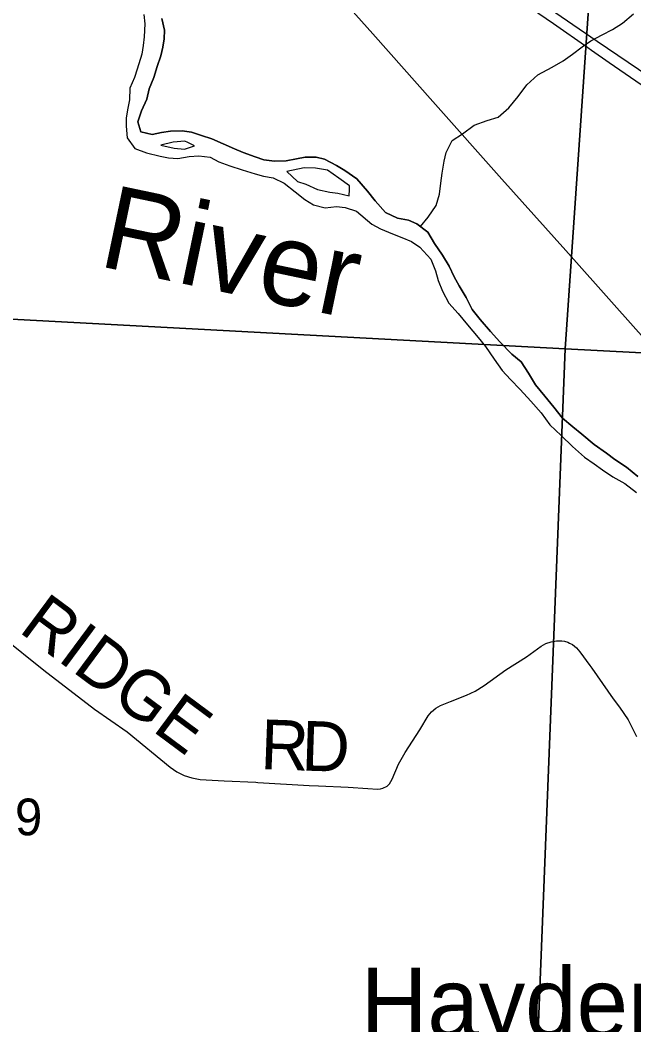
# Model space of a CAD drawing. Extents: x 0 to 34, y 0 to 22.
# Drawn here: x 5.957 to 6.658, y 19.04 to 20.186 of the extents above; entities that cross this region are included whole.
import ezdxf

# ---------------------------------------------------------------- set-up
doc = ezdxf.new("R2010")
doc.units = 0
for name, color, linetype in [('GM_X_Corporation', 7, 'Continuous'), ('GM_X_Major_River', 7, 'Continuous'), ('GM_X_Major_River_Text', 7, 'Continuous'), ('GM_X_Minor_River', 7, 'Continuous'), ('GM_X_Rail_Line', 7, 'Continuous'), ('GM_X_Section_Text', 7, 'Continuous'), ('GM_X_Township_Road', 7, 'Continuous'), ('GM_X_Township_Road_Text', 7, 'Continuous'), ('GM_X_Unincorporated_Text', 7, 'Continuous'), ('GM_X_US_Route', 7, 'Continuous')]:
    doc.layers.add(name, color=color, linetype=linetype)

msp = doc.modelspace()

# ---------------------------------------------------------------- linework, layer by layer
at = {"layer": 'GM_X_Corporation'}
for points in [[(5.6551, 20.8957), (6.6504, 20.8365), (6.5798, 19.8114), (5.5855, 19.8646)], [(6.6504, 20.8365), (7.0809, 20.8104), (7.4778, 20.7864), (7.6585, 20.7741), (7.5941, 19.7583), (6.5798, 19.8114)], [(5.5855, 19.8646), (6.5798, 19.8114), (6.5391, 18.7835), (5.5263, 18.8526)], [(6.5798, 19.8114), (7.5941, 19.7583), (7.5958, 19.6386), (7.5162, 18.7157), (6.5391, 18.7835)]]:
    msp.add_lwpolyline(points, close=True, dxfattribs=at)
at = {"layer": 'GM_X_Major_River'}
for p, q in [((6.0988, 20.1928), (6.0997, 20.1822)), ((6.1225, 20.1749), (6.1193, 20.1881)), ((6.0997, 20.1822), (6.0991, 20.1674)), ((6.0991, 20.1674), (6.098, 20.1572)), ((6.1204, 20.1555), (6.1218, 20.165)), ((6.1218, 20.165), (6.1225, 20.1749)), ((6.098, 20.1572), (6.0966, 20.1473)), ((6.1182, 20.1456), (6.1204, 20.1555)), ((6.0966, 20.1473), (6.0911, 20.1302)), ((6.1141, 20.1335), (6.1182, 20.1456)), ((6.1101, 20.1209), (6.1141, 20.1335)), ((6.0881, 20.1207), (6.0829, 20.1086)), ((6.0911, 20.1302), (6.0881, 20.1207)), ((6.1049, 20.108), (6.1101, 20.1209)), ((6.0829, 20.1086), (6.0823, 20.0953)), ((6.1023, 20.0962), (6.1049, 20.108)), ((6.096, 20.0829), (6.1023, 20.0962)), ((6.0805, 20.0858), (6.0787, 20.0748)), ((6.0823, 20.0953), (6.0805, 20.0858)), ((6.0787, 20.0748), (6.0784, 20.0653)), ((6.092, 20.0704), (6.096, 20.0829)), ((6.0784, 20.0653), (6.0796, 20.0521)), ((6.0955, 20.0587), (6.092, 20.0704)), ((6.0796, 20.0521), (6.0884, 20.04)), ((6.1084, 20.0557), (6.0955, 20.0587)), ((6.1189, 20.0581), (6.1084, 20.0557)), ((6.1291, 20.0597), (6.1189, 20.0581)), ((6.1424, 20.0598), (6.1291, 20.0597)), ((6.153, 20.0584), (6.1424, 20.0598)), ((6.1644, 20.0547), (6.153, 20.0584)), ((6.1765, 20.0507), (6.1644, 20.0547)), ((6.2023, 20.0395), (6.1765, 20.0507)), ((6.0884, 20.04), (6.1017, 20.0348)), ((6.1323, 20.0472), (6.118, 20.0438)), ((6.118, 20.0438), (6.1335, 20.0401)), ((6.1455, 20.0481), (6.1323, 20.0472)), ((6.1335, 20.0401), (6.1452, 20.039)), ((6.1452, 20.039), (6.1565, 20.0429)), ((6.1488, 20.0466), (6.1455, 20.0481)), ((6.1565, 20.0429), (6.1488, 20.0466)), ((6.2122, 20.0351), (6.2023, 20.0395)), ((6.1017, 20.0348), (6.1173, 20.0312)), ((6.1173, 20.0312), (6.1271, 20.029)), ((6.1271, 20.029), (6.1374, 20.0283)), ((6.1374, 20.0283), (6.1506, 20.0307)), ((6.1506, 20.0307), (6.1615, 20.0316)), ((6.1615, 20.0316), (6.1744, 20.0298)), ((6.1744, 20.0298), (6.1843, 20.0246)), ((6.2259, 20.0303), (6.2122, 20.0351)), ((6.2357, 20.027), (6.2259, 20.0303)), ((6.2732, 20.0281), (6.2611, 20.0257)), ((6.283, 20.03), (6.2732, 20.0281)), ((6.2955, 20.0298), (6.283, 20.03)), ((6.305, 20.0276), (6.2955, 20.0298)), ((6.3187, 20.0205), (6.305, 20.0276)), ((6.1843, 20.0246), (6.1968, 20.0202)), ((6.1968, 20.0202), (6.2109, 20.0154)), ((6.2479, 20.0252), (6.2357, 20.027)), ((6.2611, 20.0257), (6.2479, 20.0252)), ((6.282, 20.0179), (6.262, 20.0136)), ((6.2949, 20.0173), (6.282, 20.0179)), ((6.3085, 20.0151), (6.2949, 20.0173)), ((6.3282, 20.0149), (6.3187, 20.0205)), ((6.2109, 20.0154), (6.2257, 20.011)), ((6.2257, 20.011), (6.2355, 20.0084)), ((6.2355, 20.0084), (6.2465, 20.0062)), ((6.2465, 20.0062), (6.2591, 20.0003)), ((6.262, 20.0136), (6.2742, 20.0023)), ((6.3214, 20.0061), (6.3085, 20.0151)), ((6.3336, 19.9972), (6.3214, 20.0061)), ((6.3419, 20.0052), (6.3282, 20.0149)), ((6.3541, 19.9913), (6.3419, 20.0052)), ((6.2591, 20.0003), (6.2716, 19.9905)), ((6.2742, 20.0023), (6.2837, 19.999)), ((6.2837, 19.999), (6.297, 19.993)), ((6.297, 19.993), (6.311, 19.9901)), ((6.3335, 19.9929), (6.3336, 19.9972)), ((6.2716, 19.9905), (6.2827, 19.9815)), ((6.2827, 19.9815), (6.2926, 19.9756)), ((6.311, 19.9901), (6.3204, 19.9887)), ((6.3204, 19.9887), (6.3333, 19.9858)), ((6.3333, 19.9858), (6.3335, 19.9929)), ((6.3629, 19.98), (6.3541, 19.9913)), ((6.2926, 19.9756), (6.3058, 19.9723)), ((6.3058, 19.9723), (6.3187, 19.9735)), ((6.3187, 19.9735), (6.3285, 19.9725)), ((6.3285, 19.9725), (6.3414, 19.9684)), ((6.3747, 19.9668), (6.3629, 19.98)), ((6.3414, 19.9684), (6.359, 19.9534)), ((6.3884, 19.9605), (6.3747, 19.9668)), ((6.4009, 19.958), (6.3884, 19.9605)), ((6.359, 19.9534), (6.3689, 19.9482)), ((6.3689, 19.9482), (6.3825, 19.9423)), ((6.4104, 19.9539), (6.4009, 19.958)), ((6.423, 19.9445), (6.4104, 19.9539)), ((6.3825, 19.9423), (6.3935, 19.9382)), ((6.3935, 19.9382), (6.4042, 19.9338)), ((6.4307, 19.9313), (6.423, 19.9445)), ((6.4042, 19.9338), (6.4137, 19.9274)), ((6.4137, 19.9274), (6.4263, 19.9135)), ((6.4399, 19.9182), (6.4307, 19.9313)), ((6.4263, 19.9135), (6.4317, 19.9003)), ((6.4472, 19.9057), (6.4399, 19.9182)), ((6.4529, 19.8933), (6.4472, 19.9057)), ((6.4317, 19.9003), (6.4348, 19.8893)), ((6.4587, 19.8831), (6.4529, 19.8933)), ((6.4348, 19.8893), (6.4398, 19.8769)), ((6.4668, 19.8699), (6.4587, 19.8831)), ((6.4398, 19.8769), (6.4468, 19.8633)), ((6.4737, 19.8563), (6.4668, 19.8699)), ((6.4468, 19.8633), (6.4575, 19.8516)), ((6.4829, 19.8447), (6.4737, 19.8563)), ((6.4575, 19.8516), (6.4682, 19.8388)), ((6.4944, 19.8311), (6.4829, 19.8447)), ((6.4682, 19.8388), (6.4804, 19.8242)), ((6.4804, 19.8242), (6.4888, 19.814)), ((6.5054, 19.8191), (6.4944, 19.8311)), ((6.4888, 19.814), (6.4988, 19.7993)), ((6.5188, 19.8052), (6.5054, 19.8191)), ((6.4988, 19.7993), (6.508, 19.7865)), ((6.5295, 19.7966), (6.5188, 19.8052)), ((6.5379, 19.7834), (6.5295, 19.7966)), ((6.508, 19.7865), (6.5175, 19.7764)), ((6.5175, 19.7764), (6.5286, 19.7647)), ((6.546, 19.7702), (6.5379, 19.7834)), ((6.5286, 19.7647), (6.5408, 19.7516)), ((6.5567, 19.7574), (6.546, 19.7702)), ((6.567, 19.7446), (6.5567, 19.7574)), ((6.5408, 19.7516), (6.5523, 19.7381)), ((6.5769, 19.7322), (6.567, 19.7446)), ((6.5523, 19.7381), (6.5623, 19.7245)), ((6.5884, 19.7221), (6.5769, 19.7322)), ((6.5623, 19.7245), (6.5752, 19.7125)), ((6.5987, 19.7138), (6.5884, 19.7221)), ((6.5752, 19.7125), (6.5882, 19.6997)), ((6.6131, 19.7022), (6.5987, 19.7138)), ((6.5882, 19.6997), (6.6019, 19.6877)), ((6.6269, 19.6921), (6.6131, 19.7022)), ((6.6019, 19.6877), (6.613, 19.6802)), ((6.6364, 19.685), (6.6269, 19.6921)), ((6.6497, 19.6764), (6.6364, 19.685)), ((6.613, 19.6802), (6.6225, 19.6731)), ((6.6225, 19.6731), (6.6343, 19.6653)), ((6.6627, 19.6655), (6.6497, 19.6764)), ((6.6343, 19.6653), (6.648, 19.6578)), ((6.648, 19.6578), (6.6613, 19.6473))]:
    msp.add_line(p, q, dxfattribs=at)
for points in [[(6.0988, 20.1928), (6.0997, 20.1822), (6.0991, 20.1674), (6.098, 20.1572), (6.0966, 20.1473), (6.0911, 20.1302), (6.0881, 20.1207), (6.0829, 20.1086), (6.0823, 20.0953), (6.0805, 20.0858), (6.0787, 20.0748), (6.0784, 20.0653), (6.0796, 20.0521), (6.0884, 20.04), (6.1017, 20.0348), (6.1173, 20.0312), (6.1271, 20.029), (6.1374, 20.0283), (6.1506, 20.0307), (6.1615, 20.0316), (6.1744, 20.0298), (6.1843, 20.0246), (6.1968, 20.0202), (6.2109, 20.0154), (6.2257, 20.011), (6.2355, 20.0084), (6.2465, 20.0062), (6.2591, 20.0003), (6.2716, 19.9905), (6.2827, 19.9815), (6.2926, 19.9756), (6.3058, 19.9723), (6.3187, 19.9735), (6.3285, 19.9725), (6.3414, 19.9684), (6.359, 19.9534), (6.3689, 19.9482), (6.3825, 19.9423), (6.3935, 19.9382), (6.4042, 19.9338), (6.4137, 19.9274), (6.4263, 19.9135), (6.4317, 19.9003), (6.4348, 19.8893)], [(6.1193, 20.1881), (6.1225, 20.1749), (6.1218, 20.165), (6.1204, 20.1555), (6.1182, 20.1456), (6.1141, 20.1335), (6.1101, 20.1209), (6.1049, 20.108), (6.1023, 20.0962), (6.096, 20.0829), (6.092, 20.0704), (6.0955, 20.0587), (6.1084, 20.0557), (6.1189, 20.0581), (6.1291, 20.0597), (6.1424, 20.0598), (6.153, 20.0584), (6.1644, 20.0547), (6.1765, 20.0507), (6.2023, 20.0395), (6.2122, 20.0351), (6.2259, 20.0303), (6.2357, 20.027), (6.2479, 20.0252), (6.2611, 20.0257), (6.2732, 20.0281), (6.283, 20.03), (6.2955, 20.0298), (6.305, 20.0276), (6.3187, 20.0205), (6.3282, 20.0149), (6.3419, 20.0052), (6.3541, 19.9913), (6.3629, 19.98), (6.3747, 19.9668), (6.3884, 19.9605), (6.4009, 19.958), (6.4104, 19.9539), (6.423, 19.9445), (6.4307, 19.9313), (6.4399, 19.9182), (6.4472, 19.9057), (6.4529, 19.8933)], [(6.4529, 19.8933), (6.4587, 19.8831), (6.4668, 19.8699), (6.4737, 19.8563), (6.4829, 19.8447), (6.4944, 19.8311), (6.5054, 19.8191), (6.5188, 19.8052), (6.5295, 19.7966), (6.5379, 19.7834), (6.546, 19.7702), (6.5567, 19.7574), (6.567, 19.7446), (6.5769, 19.7322), (6.5884, 19.7221), (6.5987, 19.7138), (6.6131, 19.7022), (6.6269, 19.6921), (6.6364, 19.685), (6.6497, 19.6764), (6.6627, 19.6655)], [(6.4348, 19.8893), (6.4398, 19.8769), (6.4468, 19.8633), (6.4575, 19.8516), (6.4682, 19.8388), (6.4804, 19.8242), (6.4888, 19.814), (6.4988, 19.7993), (6.508, 19.7865), (6.5175, 19.7764), (6.5286, 19.7647), (6.5408, 19.7516), (6.5523, 19.7381), (6.5623, 19.7245), (6.5752, 19.7125), (6.5882, 19.6997), (6.6019, 19.6877), (6.613, 19.6802), (6.6225, 19.6731), (6.6343, 19.6653), (6.648, 19.6578), (6.6613, 19.6473)]]:
    msp.add_lwpolyline(points, dxfattribs=at)
at = {"layer": 'GM_X_Minor_River'}
for p, q in [((6.6453, 20.183), (6.6577, 20.1934)), ((6.634, 20.1757), (6.6453, 20.183)), ((6.6091, 20.1626), (6.6219, 20.1695)), ((6.6219, 20.1695), (6.634, 20.1757)), ((6.5881, 20.1476), (6.5994, 20.1557)), ((6.5994, 20.1557), (6.6091, 20.1626)), ((6.5775, 20.14), (6.5881, 20.1476)), ((6.5486, 20.1238), (6.5648, 20.1327)), ((6.5648, 20.1327), (6.5775, 20.14)), ((6.5362, 20.1123), (6.5486, 20.1238)), ((6.5261, 20.099), (6.5362, 20.1123)), ((6.5156, 20.0863), (6.5261, 20.099)), ((6.5032, 20.0756), (6.5156, 20.0863)), ((6.4907, 20.0717), (6.5032, 20.0756)), ((6.4625, 20.0567), (6.476, 20.0663)), ((6.476, 20.0663), (6.4907, 20.0717)), ((6.4508, 20.049), (6.4625, 20.0567)), ((6.4438, 20.0353), (6.4508, 20.049)), ((6.4416, 20.0254), (6.4438, 20.0353)), ((6.4394, 20.0118), (6.4416, 20.0254)), ((6.438, 20.0004), (6.4394, 20.0118)), ((6.4362, 19.9879), (6.438, 20.0004)), ((6.4326, 19.9749), (6.4362, 19.9879)), ((6.4232, 19.9616), (6.4326, 19.9749)), ((6.4148, 19.9507), (6.4232, 19.9616))]:
    msp.add_line(p, q, dxfattribs=at)
at = {"layer": 'GM_X_Rail_Line'}
msp.add_lwpolyline([(6.2563, 20.2869), (6.3601, 20.1705), (6.4286, 20.0934), (6.5075, 20.005), (6.5804, 19.9235), (6.6357, 19.8614), (6.6918, 19.7986), (6.8029, 19.674), (6.8335, 19.6396), (6.849, 19.6207), (6.8669, 19.5972), (6.8791, 19.5785), (6.8936, 19.5542), (6.9041, 19.5337), (6.9133, 19.5155), (6.921, 19.498), (6.9328, 19.4669), (6.9442, 19.4328), (6.9604, 19.3832), (6.9866, 19.3026), (7.0937, 18.9774)], dxfattribs=at)
at = {"layer": 'GM_X_Township_Road'}
for points in [[(5.9364, 19.4835), (5.9846, 19.4445), (6.0423, 19.4001), (6.0796, 19.3743), (6.1289, 19.3341), (6.1366, 19.3288), (6.1448, 19.3245), (6.1537, 19.3217), (6.1629, 19.3201), (6.1904, 19.3183), (6.2268, 19.3167), (6.2288, 19.3166)], [(6.2288, 19.3166), (6.2877, 19.3129), (6.2983, 19.3128), (6.3319, 19.3112), (6.3545, 19.3096), (6.3657, 19.3089), (6.3689, 19.3093), (6.3716, 19.3101), (6.3767, 19.3125), (6.3792, 19.3151), (6.3823, 19.3203), (6.3897, 19.3373), (6.3973, 19.3506), (6.4138, 19.3766), (6.4235, 19.3925), (6.4273, 19.3973), (6.432, 19.4013), (6.4374, 19.4045), (6.4487, 19.409), (6.4672, 19.4161), (6.4769, 19.4207), (6.4873, 19.4272), (6.5122, 19.4449), (6.5356, 19.4599), (6.5524, 19.472), (6.5578, 19.4751), (6.5637, 19.477), (6.5698, 19.478), (6.576, 19.4782), (6.5791, 19.4777), (6.5827, 19.4766), (6.5849, 19.4756), (6.5881, 19.4738), (6.5927, 19.47), (6.5965, 19.4656), (6.608, 19.45), (6.6103, 19.4468)], [(6.6103, 19.4468), (6.6346, 19.412), (6.6419, 19.4023), (6.6518, 19.3879), (6.6611, 19.3691)]]:
    msp.add_lwpolyline(points, dxfattribs=at)
at = {"layer": 'GM_X_US_Route'}
msp.add_line((6.6056, 20.1549), (6.6098, 20.152), dxfattribs=at)
for points in [[(6.1227, 20.4795), (6.1551, 20.4642), (6.1883, 20.4471), (6.2158, 20.4324), (6.2362, 20.4209), (6.2597, 20.4063), (6.2757, 20.3959), (6.3357, 20.3556), (6.3915, 20.3173), (6.4456, 20.2798), (6.5094, 20.2359), (6.5752, 20.1905), (6.6163, 20.1623)], [(6.4635, 20.2532), (6.5005, 20.2278), (6.5663, 20.1824), (6.6056, 20.1549)], [(6.6163, 20.1623), (6.628, 20.1543), (6.7342, 20.0824), (6.7573, 20.0666), (6.8409, 20.0067), (6.8952, 19.97), (6.9037, 19.9643), (6.991, 19.9031), (7.0251, 19.8804), (7.1472, 19.7962), (7.2123, 19.7524), (7.2551, 19.7211), (7.2982, 19.684), (7.3235, 19.66), (7.3455, 19.6366), (7.3709, 19.607), (7.4031, 19.5652), (7.4369, 19.509), (7.4418, 19.5003), (7.4522, 19.4812), (7.4704, 19.4451), (7.5097, 19.3661), (7.5736, 19.2384)], [(6.6098, 20.152), (6.6299, 20.138), (6.7103, 20.0828), (6.7478, 20.0568)]]:
    msp.add_lwpolyline(points, dxfattribs=at)

# ---------------------------------------------------------------- texts
at = {"layer": 'GM_X_Major_River_Text'}
msp.add_text('River', height=0.09469, rotation=348.1697, dxfattribs=at).set_placement((6.0453, 19.9061))
at = {"layer": 'GM_X_Section_Text'}
msp.add_text('19', height=0.04186, rotation=0, dxfattribs=at).set_placement((5.9205, 19.2563))
at = {"layer": 'GM_X_Township_Road_Text'}
for s, height, rotation, p in [('RIDGE', 0.05682, 323.4446, (5.9546, 19.4892)), ('R', 0.0568, 357.9348, (6.2313, 19.3319)), ('D', 0.0568, 358.1608, (6.2782, 19.3302))]:
    msp.add_text(s, height=height, rotation=rotation, dxfattribs=at).set_placement(p)
at = {"layer": 'GM_X_Unincorporated_Text'}
msp.add_text('Haydenville', height=0.078977, rotation=0, dxfattribs=at).set_placement((6.3463, 19.0262))

doc.saveas('drawing.dxf')
